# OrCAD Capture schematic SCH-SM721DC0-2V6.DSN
size C; title: module; rev: 2.1; note: <>
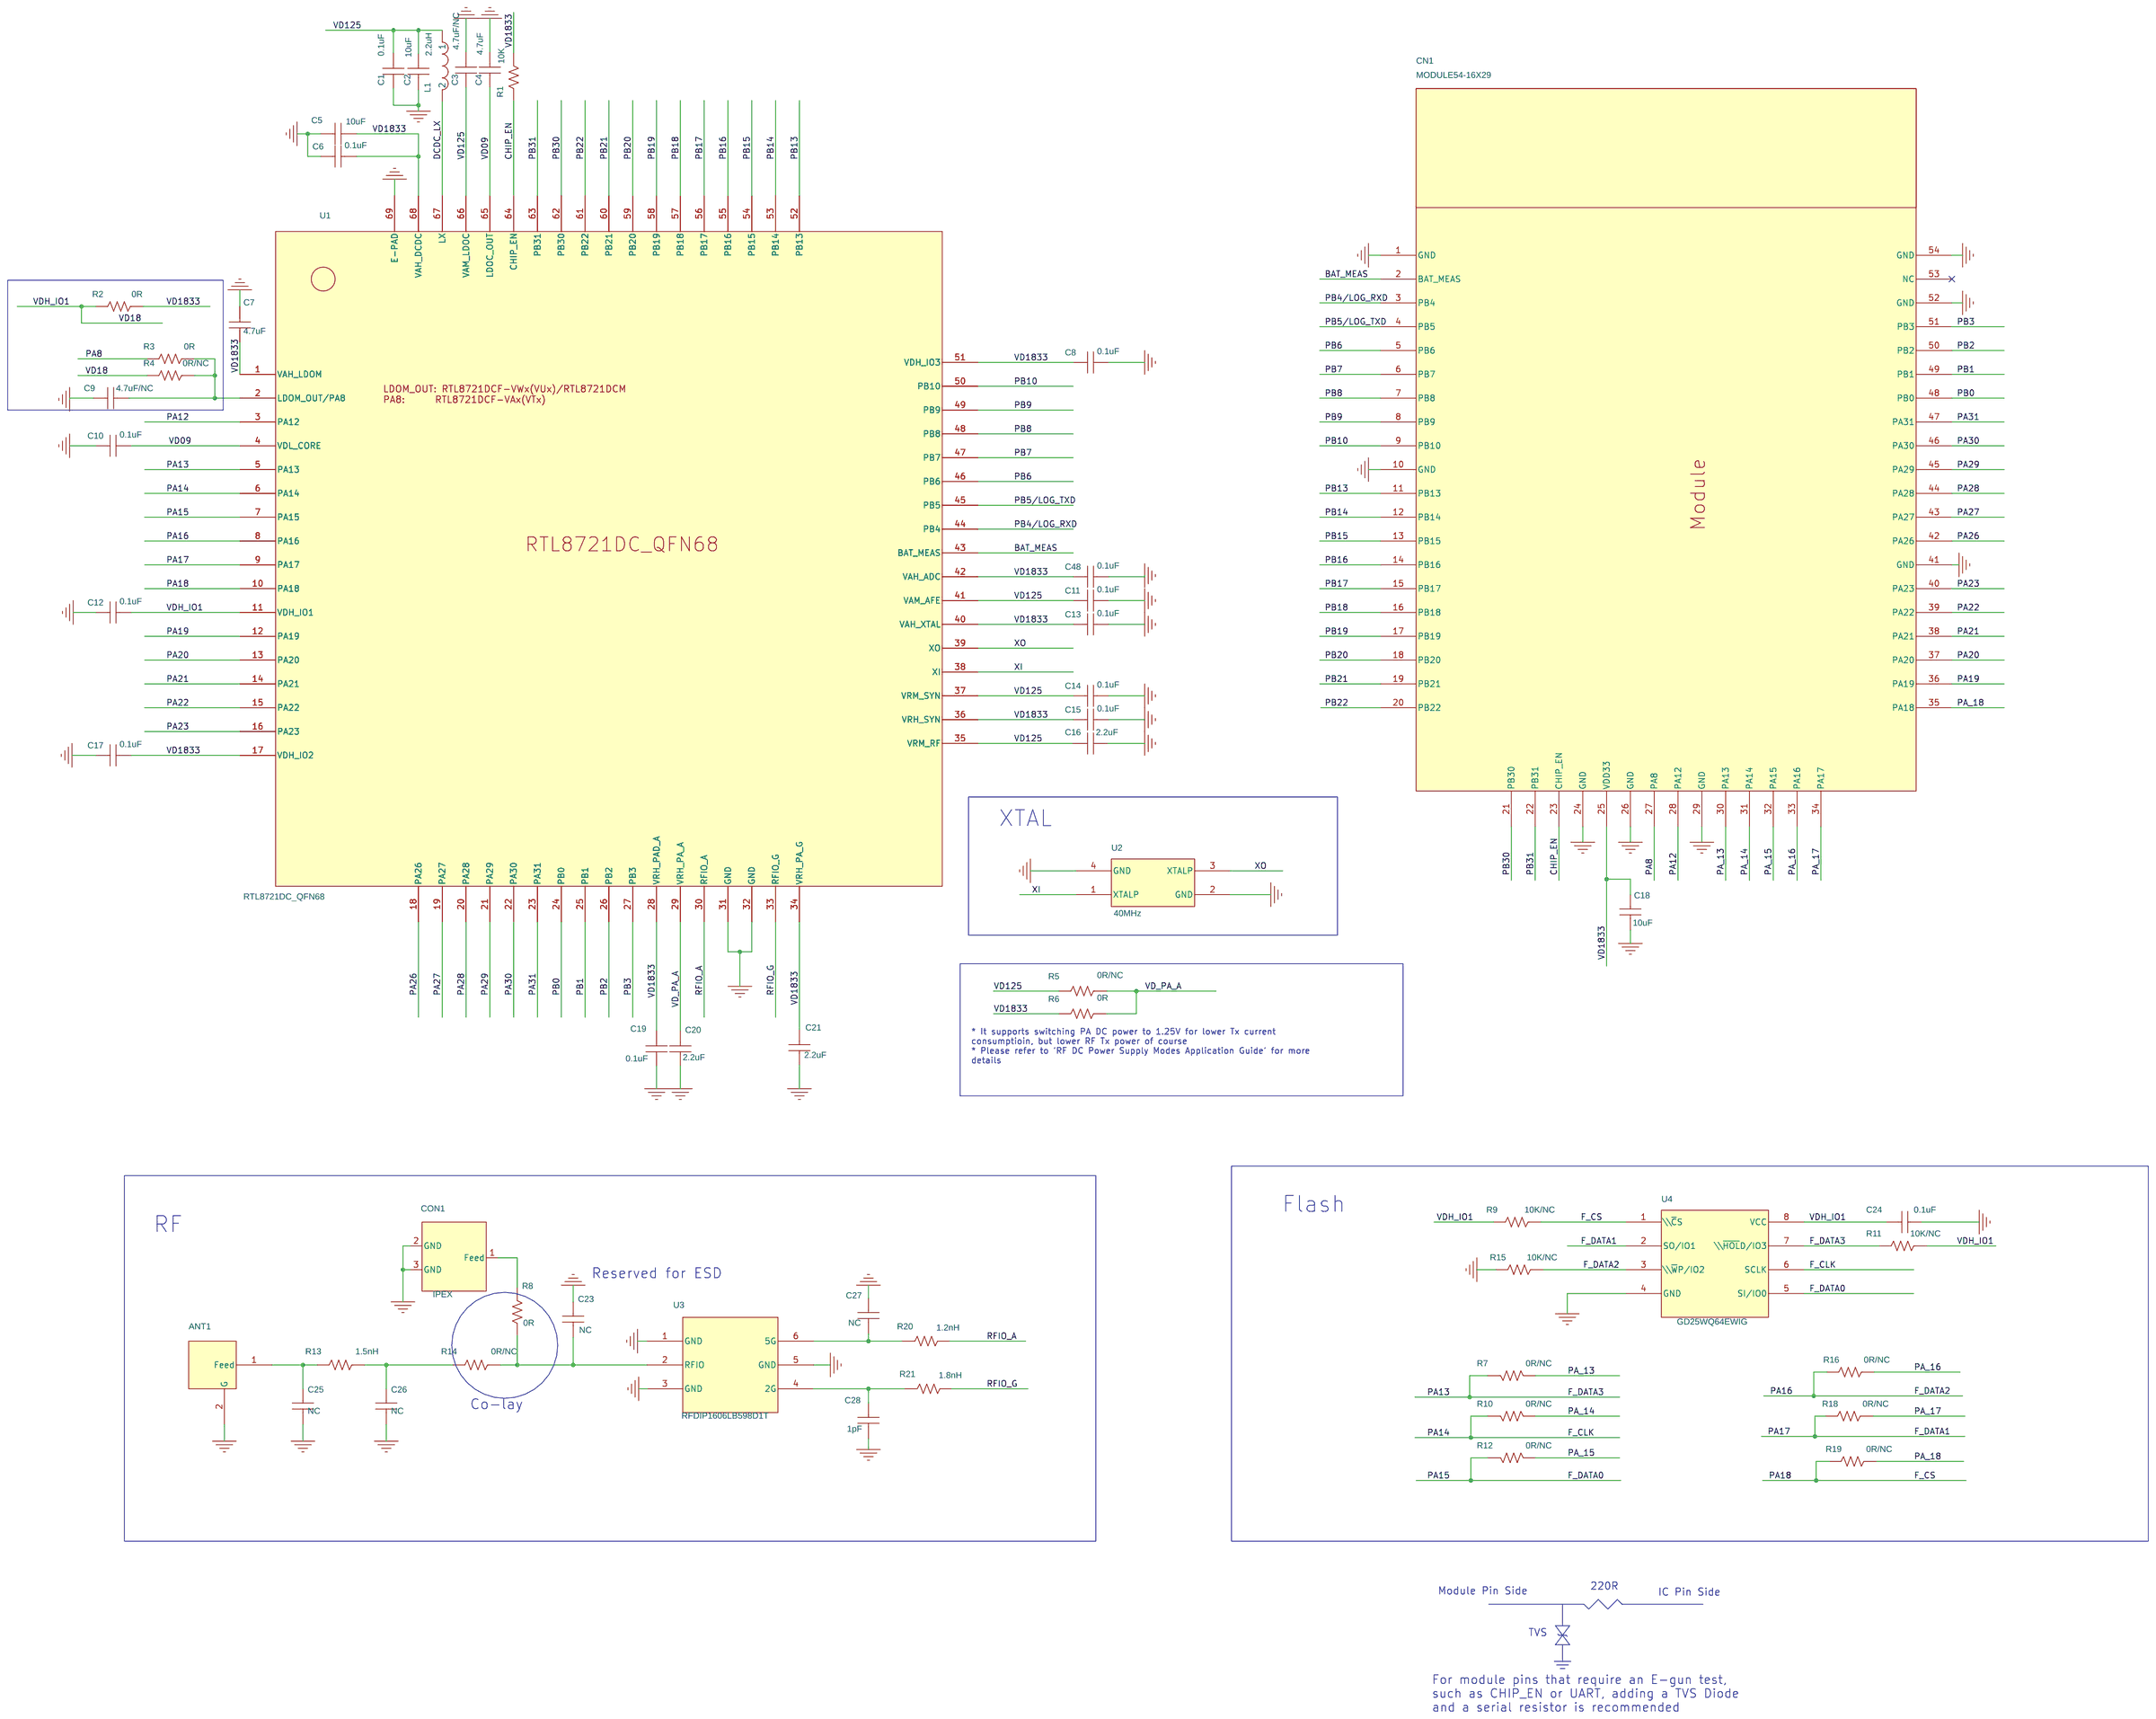
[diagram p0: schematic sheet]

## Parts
ANT1  TP  [Dplus_PANT]
C1  0.1uF  [C0201]
C2  10uF  [C0402]
C3  4.7uF/NC  [C0402]
C4  4.7uF  [C0402]
C5  10uF  [C0402]
C6  0.1uF  [C0201]
C7  4.7uF  [C0402]
C8  0.1uF  [C0201]
C9  4.7uF/NC  [C0402]
C10  0.1uF  [C0201]
C11  0.1uF  [C0201]
C12  0.1uF  [C0201]
C13  0.1uF  [C0201]
C14  0.1uF  [C0201]
C15  0.1uF  [C0201]
C16  2.2uF  [C0402]
C17  0.1uF  [C0201]
C18  10uF  [C0402]
C19  0.1uF  [C0201]
C20  2.2uF  [C0402]
C21  2.2uF  [C0402]
C23  NC  [C0201]
C24  0.1uF  [C0201]
C25  NC  [C0201]
C26  NC  [C0201]
C27  NC  [C0201]
C28  1pF  [C0201]
C48  0.1uF  [C0201]
CN1  MODULE54-16X29  [MODULE54-16X29]
CON1  IPEX  [IPEX3-1.35-0.7X2.2]
L1  2.2uH  [L2016]
R1  10K  [R0201]
R2  0R  [R0201]
R3  0R  [R0201]
R4  0R/NC  [R0201]
R5  0R/NC  [R0402]
R6  0R  [R0402]
R7  0R/NC  [R0201]
R8  0R  [R0201]
R9  10K/NC  [R0201]
R10  0R/NC  [R0201]
R11  10K/NC  [R0201]
R12  0R/NC  [R0201]
R13  1.5nH  [R0201]
R14  0R/NC  [R0201]
R15  10K/NC  [R0201]
R16  0R/NC  [R0201]
R18  0R/NC  [R0201]
R19  0R/NC  [R0201]
R20  1.2nH  [R0201]
R21  1.8nH  [R0201]
U1  RTL8721DC_QFN68  [QFN68DR-0.4-8X8-EP5.2]
U2  40MHz  [XTAL-2016]
U3  RFDIP1606LB598D1T  [DPX1608-6-0.5-0.25X0.6]
U4  GD25WQ64EWIG  [SOIC8-1.27-150-0.6X1.4]

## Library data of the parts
ANT1 = TP_2
C1 C6 C8 C10-C15 C17 C19 C24 C48 = CAPACITOR_NON-POL_0: Part Number: 0201X104K100CT; Part Type: Ceramic; Tolerance,Voltage,Dielectric,Lead Free(Y/N): ±10%，10V，X5R; Datasheet: \\172.29.17.1\cn\WLAN\WLAN2\boarddesignLIB\04_component_database\Datasheet\Capacitor\Capacitor_Walsin_MLCC.pdf
C2 C5 C18 = CAPACITOR_NON-POL_0: Part Number: 0402X106K160CT; Voltage: 16V; Datasheet: \\172.29.17.1\cn\WLAN\WLAN2\boarddesignLIB\54_component_database\Datasheet\Capacitor\Capacitor_Walsin_MLCC.pdf
C3 C4 C7 C9 = CAPACITOR_NON-POL_0: Part Number: 0402X475M160CT; Part Type: Ceramic; Tolerance,Voltage,Dielectric,Lead Free(Y/N): ±20%,16V,X5R; Datasheet: \\172.29.17.1\cn\WLAN\WLAN2\boarddesignLIB\147_component_database\Datasheet\Capacitor\Capacitor_Walsin_MLCC.pdf
C16 C20 C21 = CAPACITOR_NON-POL_0: Part Number: 0402X225K250CT; Part Type: Ceramic; Tolerance,Voltage,Dielectric,Lead Free(Y/N): ±10%,25V,X5R; Datasheet: \\172.29.17.1\cn\WLAN\WLAN2\boarddesignLIB\93_component_database\Datasheet\Capacitor\Capacitor_Walsin_MLCC.pdf
C23 C25-C28 = CAPACITOR_NON-POL_0: Part Number: RF03N1R2B250CT; Part Type: Ceramic; Tolerance,Voltage,Dielectric,Lead Free(Y/N): +/-0.1pF,25V,NPO,Y; Datasheet: \\172.29.17.1\cn\WLAN\WLAN2\boarddesignLIB\31_component_database\Datasheet\Capacitor\Capacitor_Walsin_MLCC.pdf
CN1 = R0402_14.06K_WALSIN
CON1 = TP_0: IPEX大头，IPEX1; Part Number: RFCSR-N3300-TP40; Datasheet: \\172.29.17.1\cn\WLAN\WLAN2\boarddesignLIB\01_component_database\Datasheet\Connector\RF Connector_Argosy_RFCSR-N3300-TP40_APL_Realtek (2017-03-06).pdf
L1 = Inductor_Power: Part Number: MHCD201610B-2R2M-A8L; Õ`²îÖµTolerance(nH/%),Q‚Ž(min): 1.8A,±20%
R1 R9 R11 R15 = RES_0: Part Number: WR02X103 JAL; Tolerance,Voltage,Dielectric,Lead Free(Y/N): +/-5%; Datasheet: \\172.29.17.1\cn\WLAN\WLAN2\boarddesignLIB\40_component_database\Datasheet\Resistor\Resistor_Walsin_chipR.pdf
R2-R4 R7 R8 R10 R12 R14 R16 R18 R19 = RES_0: Part Number: WR02X000PTL; Part type: Chip Resistor; Tolerance,Voltage,Dielectric,Lead Free(Y/N): JUMPER; Datasheet: \\172.29.17.1\cn\WLAN\WLAN2\boarddesignLIB\62_component_database\Datasheet\ResistorResistor_Walsin_chipR.pdf
R5 R6 = RES_0: Part Number: WR04X000PTL; Tolerance,Voltage,Dielectric,Lead Free(Y/N): JUMPER; Datasheet: \\172.29.17.1\cn\WLAN\WLAN2\boarddesignLIB\64_component_database\Datasheet\Resistor\Resistor_Walsin_chipR.pdf
R13 = RES_0: Part Number: HKQ0603W1N5S-T; Part type: Chip Resistor; Tolerance,Voltage,Dielectric,Lead Free(Y/N): JUMPER; Datasheet: \\172.29.17.1\cn\WLAN\WLAN2\boarddesignLIB\62_component_database\Datasheet\ResistorResistor_Walsin_chipR.pdf
R20 = RES_0: Part Number: HKQ0603W1N2S-T; Part type: Chip Resistor; Tolerance,Voltage,Dielectric,Lead Free(Y/N): JUMPER; Datasheet: \\172.29.17.1\cn\WLAN\WLAN2\boarddesignLIB\62_component_database\Datasheet\ResistorResistor_Walsin_chipR.pdf
R21 = RES_0: Part Number: HKQ0603W1N8S-T; Part type: Chip Resistor; Tolerance,Voltage,Dielectric,Lead Free(Y/N): JUMPER; Datasheet: \\172.29.17.1\cn\WLAN\WLAN2\boarddesignLIB\62_component_database\Datasheet\ResistorResistor_Walsin_chipR.pdf
U1 = AmebaLite_QFN68_D+_1: AmebaDplus QFN68; Part Number: AmebaDplus QFN68
U2 = XTAL_0: 9pf，25ohms，10ppm，-55-125度; Part Number: E1SB40E00090FE
U3 = DPX_0: 2nd harmonic suppressed; Datasheet: \\172.29.17.1\cn\WLAN\WLAN2\boarddesignLIB\01_component_database\Datasheet\RF Chip\DPX_Walsin_RFDIP1606LB598D1T_V01.pdf
U4 = Flash_0: Used for Module; Part Number: GD25Q16C; Datasheet: \\172.29.17.1\cn\WLAN\WLAN2\boarddesignLIB\01_component_database\Datasheet\Memory\FLASH_GigaDevice_GD25Q16CTIG.pdf

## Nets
GND: ANT1.2(G) C1.1 C2.2 C3.2 C4.2 C5.1 C6.1 C7.2 C8.2 C9.1 C10.1 C11.2 C12.1 C13.2 C14.2 C15.2 C16.1 C17.1 C18.2 C19.1 C20.1 C21.1 C23.1 C24.1 C25.2 C26.2 C27.1 C28.2 C48.2 CN1.1(GND) CN1.10(GND) CN1.24(GND) CN1.26(GND) CN1.29(GND) CN1.41(GND) CN1.52(GND) CN1.54(GND) CON1.2(GND) CON1.3(GND) R15.1 U1.31(GND) U1.32(GND) U1.69(E-PAD) U2.2(GND) U2.4(GND) U3.1(GND) U3.3(GND) U3.5(GND) U4.4(GND)
BAT_MEAS: CN1.2(BAT_MEAS) U1.43(BAT_MEAS)
CHIP_EN: CN1.23(CHIP_EN) R1.1 U1.64(CHIP_EN)
DCDC_LX: L1.2 U1.67(LX)
F_CLK: R10.2 U1.6(PA14) U4.6(SCLK)
F_CS: R9.2 R19.1 U1.10(PA18) U4.1(\\~{C}S)
F_DATA0: R12.2 U1.7(PA15) U4.5(SI/IO0)
F_DATA1: R18.1 U1.9(PA17) U4.2(SO/IO1)
F_DATA2: R15.2 R16.1 U1.8(PA16) U4.3(\\~{W}P/IO2)
F_DATA3: R7.2 R11.1 U1.5(PA13) U4.7(\\~{HOL}D/IO3)
PA8: CN1.27(PA8) R3.1
PA12: CN1.28(PA12) U1.3(PA12)
PA19: CN1.36(PA19) U1.12(PA19)
PA20: CN1.37(PA20) U1.13(PA20)
PA21: CN1.38(PA21) U1.14(PA21)
PA22: CN1.39(PA22) U1.15(PA22)
PA23: CN1.40(PA23) U1.16(PA23)
PA26: CN1.42(PA26) U1.18(PA26)
PA27: CN1.43(PA27) U1.19(PA27)
PA28: CN1.44(PA28) U1.20(PA28)
PA29: CN1.45(PA29) U1.21(PA29)
PA30: CN1.46(PA30) U1.22(PA30)
PA31: CN1.47(PA31) U1.23(PA31)
PA_13: CN1.30(PA13) R7.1
PA_14: CN1.31(PA14) R10.1
PA_15: CN1.32(PA15) R12.1
PA_16: CN1.33(PA16) R16.2
PA_17: CN1.34(PA17) R18.2
PA_18: CN1.35(PA18) R19.2
PB0: CN1.48(PB0) U1.24(PB0)
PB1: CN1.49(PB1) U1.25(PB1)
PB2: CN1.50(PB2) U1.26(PB2)
PB3: CN1.51(PB3) U1.27(PB3)
PB4/LOG_RXD: CN1.3(PB4) U1.44(PB4)
PB5/LOG_TXD: CN1.4(PB5) U1.45(PB5)
PB6: CN1.5(PB6) U1.46(PB6)
PB7: CN1.6(PB7) U1.47(PB7)
PB8: CN1.7(PB8) U1.48(PB8)
PB9: CN1.8(PB9) U1.49(PB9)
PB10: CN1.9(PB10) U1.50(PB10)
PB13: CN1.11(PB13) U1.52(PB13)
PB14: CN1.12(PB14) U1.53(PB14)
PB15: CN1.13(PB15) U1.54(PB15)
PB16: CN1.14(PB16) U1.55(PB16)
PB17: CN1.15(PB17) U1.56(PB17)
PB18: CN1.16(PB18) U1.57(PB18)
PB19: CN1.17(PB19) U1.58(PB19)
PB20: CN1.18(PB20) U1.59(PB20)
PB21: CN1.19(PB21) U1.60(PB21)
PB22: CN1.20(PB22) U1.61(PB22)
PB30: CN1.21(PB30) U1.62(PB30)
PB31: CN1.22(PB31) U1.63(PB31)
RFIO_A: R20.1 U1.30(RFIO_A)
RFIO_G: R21.1 U1.33(RFIO_G)
VD09: C4.1 C10.2 U1.4(VDL_CORE) U1.65(LDOC_OUT)
VD18: C12.2 C24.2 R2.1 R4.1 R9.1 R11.2 U1.11(VDH_IO1) U4.8(VCC)
VD125: C1.2 C2.1 C3.1 C11.1 C14.1 C16.2 L1.1 R5.1 U1.35(VRM_RF) U1.37(VRM_SYN) U1.41(VAM_AFE) U1.66(VAM_LDOC)
VD1833: C5.2 C6.2 C7.1 C8.1 C13.1 C15.1 C17.2 C18.1 C19.2 C21.2 C48.1 CN1.25(VDD33) R1.2 R2.2 R6.1 U1.1(VAH_LDOM) U1.17(VDH_IO2) U1.28(VRH_PAD_A) U1.34(VRH_PA_G) U1.36(VRH_SYN) U1.40(VAH_XTAL) U1.42(VAH_ADC) U1.51(VDH_IO3) U1.68(VAH_DCDC)
VD_PA_A: C20.2 R5.2 R6.2 U1.29(VRH_PA_A)
XI: U1.38(XI) U2.1(XTALP)
XO: U1.39(XO) U2.3(XTALP)
N05434: ANT1.1(Feed) C25.1 R13.1
N06126: C26.1 R13.2 R14.1
N16320223: C23.2 R8.1 R14.2 U3.2(RFIO)
N16320510: CON1.1(Feed) R8.2
N16392580: C9.2 R3.2 R4.2 U1.2(LDOM_OUT/PA8)
N16487419: C27.2 R20.2 U3.6(5G)
N16487437: C28.1 R21.2 U3.4(2G)

Not connected (* = marked no-connect by the designer): CN1 53(NC)*

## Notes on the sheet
- XTAL
- * It supports switching PA DC power to 1.25V for lower Tx current
  consumptioin, but lower RF Tx power of course
  * Please refer to 'RF DC Power Supply Modes Application Guide' for more
  details
- Flash
- RF
- Reserved for ESD
- Co-lay
- 220R
- Module Pin Side
- IC Pin Side
- TVS
- For module pins that require an E-gun test,
  such as CHIP_EN or UART, adding a TVS Diode
  and a serial resistor is recommended
